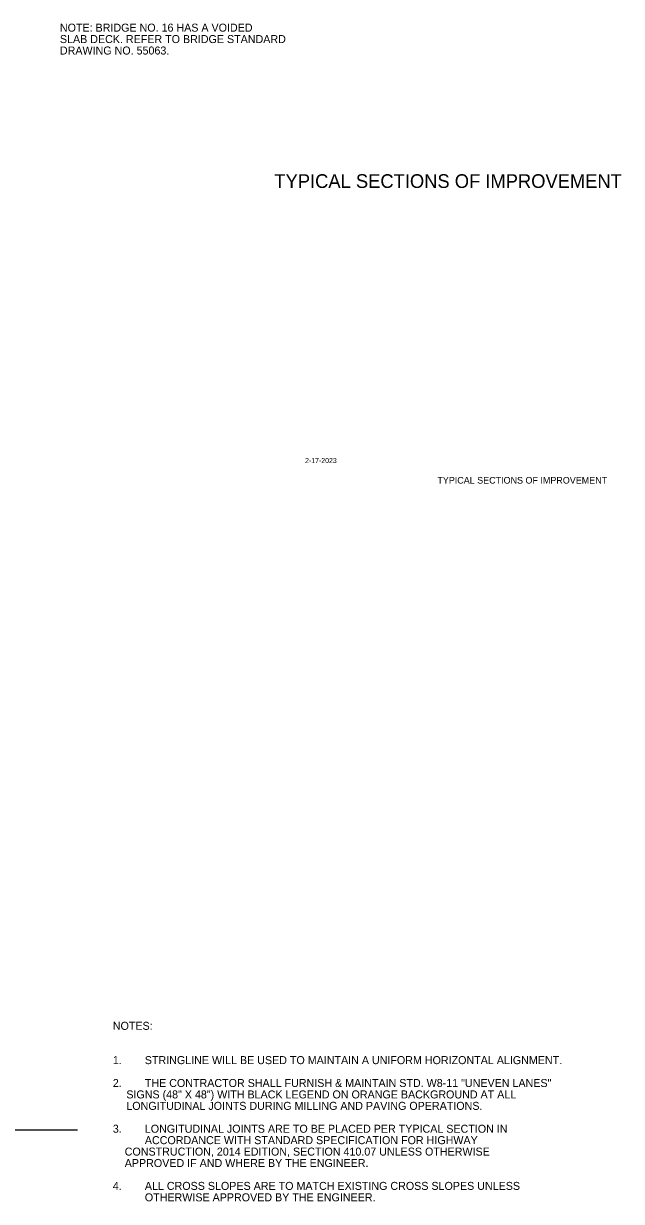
# Model space of a CAD drawing. Extents: x 549600 to 1930787, y -1955432 to 596640.
# Drawn here: x 552023 to 552546, y -1953818 to -1952788 of the extents above; entities that cross this region are included whole.
import ezdxf

# ---------------------------------------------------------------- set-up
doc = ezdxf.new("R2010")
doc.units = 0
for name, color, linetype in [('R_Border', 7, 'Continuous'), ('R_Border Notes', 7, 'Continuous'), ('R_Border Prem', 7, 'Continuous')]:
    doc.layers.add(name, color=color, linetype=linetype)

msp = doc.modelspace()

# ---------------------------------------------------------------- linework, layer by layer
at = {"layer": 'R_Border'}
msp.add_line((551009, -1953756), (552070.2, -1953756), dxfattribs=at)

# ---------------------------------------------------------------- texts
msp.add_text('TYPICAL SECTIONS OF IMPROVEMENT', height=12, rotation=360, dxfattribs=at).set_placement((552242.3, -1952932.1))
at = {"layer": 'R_Border Notes'}
for s, p in [('NOTE: BRIDGE NO. 16 HAS A VOIDED', (552054.7, -1952795.4)), ('SLAB DECK. REFER TO BRIDGE STANDARD', (552054.7, -1952805.4)), ('DRAWING NO. 55063.', (552054.7, -1952815.4)), ('NOTES: ', (552101, -1953668.4)), ('1.', (552101, -1953698.4)), ('STRINGLINE WILL BE USED TO MAINTAIN A UNIFORM HORIZONTAL ALIGNMENT.', (552129, -1953698.4)), ('2.', (552101, -1953718.4)), ('THE CONTRACTOR SHALL FURNISH & MAINTAIN STD. W8-11 "UNEVEN LANES" ', (552129, -1953718.4)), ('    SIGNS (48" X 48") WITH BLACK LEGEND ON ORANGE BACKGROUND AT ALL ', (552102.4, -1953728.4)), ('    LONGITUDINAL JOINTS DURING MILLING AND PAVING OPERATIONS.', (552102.4, -1953738.4)), ('3.', (552101, -1953758.4)), ('LONGITUDINAL JOINTS ARE TO BE PLACED PER TYPICAL SECTION IN ', (552129, -1953758.4)), ('ACCORDANCE WITH STANDARD SPECIFICATION FOR HIGHWAY', (552129, -1953768.4)), ('    CONSTRUCTION, 2014 EDITION, SECTION 410.07 UNLESS OTHERWISE', (552101, -1953778.4)), ('    APPROVED IF AND WHERE BY THE ENGINEER.', (552101, -1953788.4)), ('4.', (552101, -1953808.4)), ('ALL CROSS SLOPES ARE TO MATCH EXISTING CROSS SLOPES UNLESS ', (552129, -1953808.4)), ('OTHERWISE APPROVED BY THE ENGINEER.', (552129, -1953818.4))]:
    msp.add_text(s, height=7, dxfattribs=at).set_placement(p)
at = {"layer": 'R_Border Prem'}
msp.add_text('2-17-2023', height=4.4, dxfattribs=at).set_placement((552269.2, -1953172.7))
msp.add_text('TYPICAL SECTIONS OF IMPROVEMENT', height=5.862, rotation=360, dxfattribs=at).set_placement((552384.9, -1953190.7))

doc.saveas('drawing.dxf')
